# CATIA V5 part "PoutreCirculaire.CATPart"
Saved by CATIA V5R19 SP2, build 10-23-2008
Part number: PoutreCirculaire
Bounding box of the stored display mesh (mm): x 0 to 278, y -35 to 35, z -34.808 to 34.808
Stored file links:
  D:\SCHOOL\FRANCE\BANC_POUTRE_EN_MOUSSE\PoutreCirculaire.CATPart
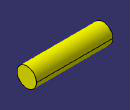
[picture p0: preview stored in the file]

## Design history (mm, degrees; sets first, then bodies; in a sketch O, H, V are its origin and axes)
AxisSystem1: origin (0, 0, 0), X (1, 0, 0), Y (0, 1, 0), Z (0, 0, 1)
Body1 (main body)
  Sketch1 on yz-plane, origin (0, 0, 0), H (0, 1, 0), V (0, 0, 1)
    circle A1 centre (0, 0) radius 35
    radius A1 = 35
  Pad1: profile Sketch1, direction (1, 0, 0), length 278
